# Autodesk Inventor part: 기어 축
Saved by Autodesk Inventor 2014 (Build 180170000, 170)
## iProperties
Created: 2025-12
Part Number: 기어 축
Material: 일반
Document SubType Name: Modeling
Designer: dg
Density: 1 g/cm^3
Appearance: 기본값
Author: dg
Author: jhkim
Creation Date: 2025-11-19
Sending System: Autodesk Inventor 2026
Preprocessor: ST-DEVELOPER v20.1
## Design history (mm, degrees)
node "기어 축1"
node "솔리드1"
node "기준1"
